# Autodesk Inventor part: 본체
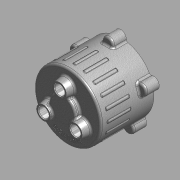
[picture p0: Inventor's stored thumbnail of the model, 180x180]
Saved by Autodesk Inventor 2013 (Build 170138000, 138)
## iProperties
Created: 2015-11
Part Number: 본체
Document SubType Name: 모델링
Designer: mdu
Material: 알루미늄 6061
Density: 1 g/cm^3
변환 표준: STEP AP214IS
파일 이름: C:\Users\SeoGD\Desktop\?쒗뿕\紐몄껜.stp
전처리기: Build: 253, Release: 2010 SP1 - Date: Wed 07/29/2009
전송 단위: 밀리미터
불확실성: 0.01
Author: mdu
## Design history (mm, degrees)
sketch "스케치2"
  geometry: C1 r 50 at (0, 0); 1 further point
  constraints: 1 centre point, 1 coincident
  dimensions: "d9" = 100 diameter of C1
extrude "돌출2" new body sketch "스케치2" distance "d10" = 80; taper "d11" = 0 deg
feature "쉘1" dims "d12" = 5
sketch "스케치3" dims "d13" = 55
  geometry: C1 r 7.5 at (0, 27.5); C2 r 12.5 at (0, 27.5); 2 further points
  constraints: 2 centre point, 2 coincident, 2 vertical alignment, 2 other
  dimensions: "d14" = 15 diameter of C1; "d15" = 25 diameter of C2
extrude "돌출3" join sketch "스케치3" distance "d16" = 12; taper "d17" = -10 deg
hole "구멍2" diameter "d20" = 15; stored, may be unused: countersink angle "d24" = 90 deg, drill point angle "d26" = 118 deg; dims "d18" = 10, "d19" = 10, "d21" = 6, "d22" = 4, "d23" = 2, "d25" = 15
chamfer "모따기1" distance "d27" = 1; stored, may be unused: second distance "d28" = 2, angle "d29" = 45 deg
sketch "스케치4"
  geometry: L1 (0, 0)-(0, 88); L2 (0, 70)-(13.16, 70); L3 (-45, 75)-(45, 75) reference; L4 (-50, 80)-(50, 80) reference; L5 (13.16, 70)-(14.5, 75); L6 (20, 80)-(20, 88); L7 (20, 88)-(0, 88); L8 (20, 80)-(14.5, 75)
  constraints: 12 end point, 3 point on line, 2 perpendicular, 1 vertical
  dimensions: "d34" = 40 diameter of L6 L1; "d35" = 105 deg angle of L5 L3; "d36" = 5 distance between parallel lines of L2 L3; "d37" = 8 distance between parallel lines of L7 L4; "d51" = 29 diameter of L5.end L1
revolve "회전1" sketch "스케치4" stored, may be unused: angle "d38" = 90 deg
hole "구멍3" diameter "d41" = 15; stored, may be unused: countersink angle "d45" = 90 deg, drill point angle "d47" = 0 deg; dims "d39" = 10, "d40" = 10, "d42" = 6, "d43" = 22, "d44" = 13, "d46" = 15
chamfer "모따기2" distance "d48" = 1; stored, may be unused: second distance "d49" = 2, angle "d50" = 45 deg
fillet "모깎기1" dims "d52" = 3
fillet "모깎기2" dims "d53" = 3, "d72" = 0.2
sketch "스케치5"
  geometry: A1 r 50 centre (0, 0) between (50, 0) and (-8.074, 49.344) reference; A2 r 8.5 centre (0, 52) between (8.074, 49.344) and (-8.074, 49.344); 1 further point
  constraints: 5 point on circle, 1 centre point, 1 horizontal alignment
  dimensions: "d54" = 90 deg dimension on point (0, 0) A2.centre A1.start; "d55" = 52 distance of A2.centre point (0, 0); "d56" = 17 diameter of A2
extrude "돌출4" join sketch "스케치5" distance "d57" = 20; taper "d58" = 0 deg
fillet "모깎기3" dims "d59" = 3
hole "구멍4" diameter "d62" = 4.134; stored, may be unused: countersink angle "d66" = 90 deg, drill point angle "d68" = 118 deg; dims "d60" = 10, "d61" = 10, "d63" = 12, "d64" = 22, "d65" = 13, "d67" = 15
sketch "스케치6"
  geometry: C1 r 47 at (0, 0) reference; C2 r 42.5 at (0, 0); 1 further point
  constraints: 1 centre point, 1 coincident, 1 other
  dimensions: "d73" = 85 diameter of C2
feature "엠보싱1" sketch "스케치6" dims "d74" = 0.5, "d75" = 0
node "작업 평면1"
sketch "스케치7"
  geometry: A1 r 50 centre (0, 0) between (5.144, 49.735) and (-5.144, 49.735) reference; A2 r 3 centre (0, 47.916) between (2.204, 49.951) and (-2.204, 49.951); 1 further point
  constraints: 4 point on circle, 1 centre point, 1 vertical alignment
  dimensions: "d77" = 3 radius of A2
extrude "돌출5" join sketch "스케치7" distance "d79" = 35; taper "d80" = 0 deg
fillet "모깎기4" dims "d81" = 1
fillet "모깎기5" dims "d82" = 1
node "솔리드1"
node "솔리드 본체"
node "곡면 본체"
pattern_circular "원형 패턴1" dims "d31" = 360 deg
pattern_circular "원형 패턴2" dims "d70" = 360 deg
pattern_circular "원형 패턴3" dims "d84" = 360 deg
node "솔리드2"
